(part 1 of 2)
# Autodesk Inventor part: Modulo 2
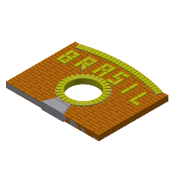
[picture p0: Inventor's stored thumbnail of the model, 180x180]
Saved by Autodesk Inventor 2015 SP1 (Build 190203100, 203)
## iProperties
Created: 2015-04
Part Number: Modulo 2
Material: Generic
Document SubType Name: Modeling
Designer: treina2
Density: 1 g/cm^3
Appearance: Default
Author: treina2
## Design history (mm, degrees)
sketch "Sketch1"
  geometry: L1 (740, 1360)-(740, 1418) reference; L2 (954, 1088)-(954, 1146) reference; L3 (740, 1088)-(740, 1146) reference; L4 (740, 1292)-(740, 1350) reference; L5 (954, 1224)-(954, 1282) reference; L6 (954, 1360)-(954, 1418) reference; L7 (954, 1292)-(954, 1350) reference; L8 (954, 1156)-(954, 1214) reference; L9 (740, 1156)-(740, 1214) reference; L10 (740, 1224)-(740, 1282) reference; L11 (1990, 534)-(1990, 544) reference; L12 (1990, 1350)-(1990, 1360) reference; L13 (740, 262)-(500, 262) reference; L14 (500, 262)-(500, 204) reference; L15 (1875, 136)-(1990, 136) reference; L16 (1990, 136)-(1990, 194) reference; L17 (1990, 194)-(1875, 194) reference; L18 (1875, 194)-(1875, 136) reference; L19 (250, 68)-(490, 68) reference; L20 (490, 68)-(490, 126) reference; L21 (490, 126)-(250, 126) reference; L22 (250, 126)-(250, 68) reference; L23 (750, 68)-(777.045, 68) reference; L24 (1250, 204)-(1490, 204) reference; L25 (1490, 204)-(1490, 262) reference; L26 (1490, 262)-(1250, 262) reference; L27 (1250, 262)-(1250, 204) reference; L28 (1500, 204)-(1740, 204) reference; L29 (1740, 204)-(1740, 262) reference; L30 (1740, 262)-(1500, 262) reference; L31 (1500, 262)-(1500, 204) reference; L32 (125, 136)-(365, 136) reference; L33 (365, 136)-(365, 194) reference; L34 (365, 194)-(125, 194) reference; L35 (125, 194)-(125, 136) reference; L36 (0, 476)-(240, 476) reference; L37 (240, 476)-(240, 534) reference; L38 (240, 534)-(0, 534) reference; L39 (0, 534)-(0, 476) reference; L40 (115, 408)-(0, 408) reference; L41 (0, 408)-(0, 466) reference; L42 (0, 466)-(115, 466) reference; L43 (115, 466)-(115, 408) reference; L44 (1750, 1020)-(1990, 1020) reference; L45 (1990, 1020)-(1990, 1078) reference; L46 (1990, 1078)-(1750, 1078) reference; L47 (1750, 1078)-(1750, 1020) reference; L48 (375, 680)-(570.34, 680) reference; L49 (1500, 884)-(1740, 884) reference; L50 (1740, 884)-(1740, 942) reference; L51 (1740, 942)-(1500, 942) reference; L52 (1500, 942)-(1500, 884) reference; L53 (1750, 884)-(1990, 884) reference; L54 (1990, 884)-(1990, 942) reference; L55 (1990, 942)-(1750, 942) reference; L56 (1750, 942)-(1750, 884) reference; L57 (1250, 1292)-(1422, 1292) reference; L58 (750, 1020)-(764.401, 1020) reference; L59 (250, 1214)-(250, 1156) reference; L60 (250, 1156)-(308, 1156) reference; L61 (750, 1258)-(750, 1418) reference; L62 (750, 1418)-(808, 1418) reference; L63 (808, 1418)-(808, 1258) reference; L64 (808, 1258)-(750, 1258) reference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; C1 r 300 at (995, 663) reference; C2 r 300 at (995, 663) reference; C3 r 300 at (995, 663) reference; C4 r 300 at (995, 663) reference; C5 r 300 at (995, 663) reference; C6 r 300 at (995, 663) reference; A1 r 425 centre (995, 663) between (749.611, 1010) and (683.385, 952) reference; A2 r 2840.721 centre (995, -1354.721) between (490, 1440.752) and (423.896, 1428) reference; A3 r 425 centre (995, 663) between (1411.413, 748) and (1395.22, 806) reference; A4 r 425 centre (995, 663) between (1419.66, 680) and (1413.33, 738) reference; A5 r 425 centre (995, 663) between (863.689, 258.794) and (990, 238.029) reference; A6 r 425 centre (995, 663) between (594.78, 806) and (578.587, 748) reference; A7 r 2840.721 centre (995, -1354.721) between (1615, 1417.516) and (1612.83, 1418) reference; A8 r 425 centre (995, 663) between (903.348, 1078) and (764.401, 1020) reference; A9 r 425 centre (995, 663) between (1376.649, 476) and (1399.949, 534) reference; A10 r 425 centre (995, 663) between (662.735, 398) and (718.783, 340) reference; A11 r 425 centre (995, 663) between (1358.021, 884) and (1315.599, 942) reference; A12 r 425 centre (995, 663) between (1365, 872.105) and (1363.923, 874) reference; A13 r 425 centre (995, 663) between (1225.599, 1020) and (1086.652, 1078) reference; A14 r 425 centre (995, 663) between (1403, 544) and (1415.6, 602) reference; A15 r 425 centre (995, 663) between (1416.929, 612) and (1419.942, 670) reference; A16 r 425 centre (995, 663) between (1161.565, 272) and (1259.076, 330) reference; A17 r 425 centre (995, 663) between (1271.217, 340) and (1327.265, 398) reference; A18 r 425 centre (995, 663) between (1335, 408) and (1365, 453.895) reference; A19 r 425 centre (995, 663) between (574.4, 602) and (587, 544) reference; A20 r 425 centre (995, 663) between (590.051, 534) and (613.351, 476) reference; A21 r 425 centre (995, 663) between (1000, 238.029) and (1126.311, 258.794) reference; A22 r 425 centre (995, 663) between (576.67, 738) and (570.34, 680) reference; A23 r 425 centre (995, 663) between (730.924, 330) and (828.435, 272) reference; A24 r 425 centre (995, 663) between (615, 853.329) and (598.495, 816) reference; A25 r 425 centre (995, 663) between (626.077, 874) and (625, 872.105) reference; A26 r 2840.721 centre (995, -1354.721) between (1831.651, 1360) and (1625, 1415.26) reference; A27 r 425 centre (995, 663) between (674.401, 942) and (631.979, 884) reference; A28 r 2840.721 centre (995, -1354.721) between (365, 1415.26) and (158.349, 1360) reference; A29 r 2840.721 centre (995, -1354.721) between (990, 1485.996) and (750, 1475.415) reference; A30 r 2840.721 centre (995, -1354.721) between (740, 1474.532) and (500, 1442.54) reference; A31 r 2840.721 centre (995, -1354.721) between (377.17, 1418) and (375, 1417.516) reference; A32 r 425 centre (995, 663) between (570.058, 670) and (573.071, 612) reference; A33 r 425 centre (995, 663) between (1391.505, 816) and (1375, 853.329) reference; A34 r 425 centre (995, 663) between (625, 453.895) and (655, 408) reference; A35 r 425 centre (995, 663) between (1306.615, 952) and (1240.389, 1010) reference; A36 r 2840.721 centre (995, -1354.721) between (1490, 1442.54) and (1250, 1474.532) reference; A37 r 2840.721 centre (995, -1354.721) between (1240, 1475.415) and (1000, 1485.996) reference; A38 r 2840.721 centre (995, -1354.721) between (1566.104, 1428) and (1500, 1440.752) reference; 1 further point
  constraints: 2472 end point, 508 horizontal, 481 vertical, 127 point on line, 76 point on circle, 44 centre point, 1 midpoint, 1471 other
extrude "Extrusion1" new body sketch "Sketch1" distance "d0" = 115 (= T_P_L); taper "d1" = 0 deg
extrude "Extrusion2" new body sketch "Sketch1" distance "d2" = 115 (= T_P_L); taper "d3" = 0 deg
extrude "Extrusion3" new body sketch "Sketch1" distance "d4" = 115 (= T_P_L); taper "d5" = 0 deg
extrude "Extrusion4" new body sketch "Sketch1" distance "d6" = 115 (= T_P_L); taper "d7" = 0 deg
extrude "Extrusion6" new body sketch "Sketch1" distance "d10" = 115 (= T_P_L); taper "d11" = 0 deg
extrude "Extrusion7" new body sketch "Sketch1" distance "d12" = 115 (= T_P_L); taper "d13" = 0 deg
extrude "Extrusion8" new body sketch "Sketch1" distance "d14" = 115 (= T_P_L); taper "d15" = 0 deg
extrude "Extrusion9" new body sketch "Sketch1" distance "d16" = 115 (= T_P_L); taper "d17" = 0 deg
extrude "Extrusion10" new body sketch "Sketch1" distance "d18" = 115 (= T_P_L); taper "d19" = 0 deg
extrude "Extrusion11" new body sketch "Sketch1" distance "d20" = 115 (= T_P_L); taper "d21" = 0 deg
extrude "Extrusion12" new body sketch "Sketch1" distance "d22" = 115 (= T_P_L); taper "d23" = 0 deg
extrude "Extrusion13" new body sketch "Sketch1" distance "d24" = 115 (= T_P_L); taper "d25" = 0 deg
extrude "Extrusion14" new body sketch "Sketch1" distance "d26" = 115 (= T_P_L); taper "d27" = 0 deg
extrude "Extrusion15" new body sketch "Sketch1" distance "d28" = 115 (= T_P_L); taper "d29" = 0 deg
pattern_linear "Rectangular Pattern1" dims "d32" = 136 (= 2 x T_P_P + 2 x GAP)
pattern_linear "Rectangular Pattern2" dims "d35" = 136 (= 2 x T_P_P + 2 x GAP)
pattern_linear "Rectangular Pattern3" dims "d38" = 136 (= 2 x T_P_P + 2 x GAP)
pattern_linear "Rectangular Pattern4" dims "d41" = 136 (= 2 x T_P_P + 2 x GAP)
pattern_linear "Rectangular Pattern5" dims "d44" = 136 (= 2 x T_P_P + 2 x GAP)
pattern_linear "Rectangular Pattern6" dims "d47" = 136 (= 2 x T_P_P + 2 x GAP)
extrude "Extrusion16" new body sketch "Sketch1" distance "d48" = 115 (= T_P_L); taper "d49" = 0 deg
extrude "Extrusion17" new body sketch "Sketch1" distance "d50" = 115 (= T_P_L); taper "d51" = 0 deg
extrude "Extrusion18" new body sketch "Sketch1" distance "d52" = 115 (= T_P_L); taper "d53" = 0 deg
pattern_linear "Rectangular Pattern7" dims "d56" = 136 (= 2 x T_P_P + 2 x GAP)
pattern_linear "Rectangular Pattern8" dims "d59" = 136 (= 2 x T_P_P + 2 x GAP)
pattern_linear "Rectangular Pattern9" dims "d62" = 136 (= 2 x T_P_P + 2 x GAP)
pattern_linear "Rectangular Pattern10" dims "d65" = 136 (= 2 x T_P_P + 2 x GAP)
pattern_linear "Rectangular Pattern11" dims "d68" = 136 (= 2 x T_P_P + 2 x GAP)
extrude "Extrusion19" new body sketch "Sketch1" distance "d69" = 115 (= T_P_L); taper "d70" = 0 deg
extrude "Extrusion20" new body sketch "Sketch1" distance "d71" = 115 (= T_P_L); taper "d72" = 0 deg
extrude "Extrusion21" new body sketch "Sketch1" distance "d73" = 115 (= T_P_L); taper "d74" = 0 deg
extrude "Extrusion22" new body sketch "Sketch1" distance "d75" = 115 (= T_P_L); taper "d76" = 0 deg
extrude "Extrusion25" new body sketch "Sketch1" distance "d81" = 115 (= T_P_L); taper "d82" = 0 deg
extrude "Extrusion26" new body sketch "Sketch1" distance "d83" = 115 (= T_P_L); taper "d84" = 0 deg
extrude "Extrusion27" new body sketch "Sketch1" distance "d85" = 115 (= T_P_L); taper "d86" = 0 deg
extrude "Extrusion28" new body sketch "Sketch1" distance "d87" = 115 (= T_P_L); taper "d88" = 0 deg
extrude "Extrusion29" new body sketch "Sketch1" distance "d89" = 115 (= T_P_L); taper "d90" = 0 deg
extrude "Extrusion30" new body sketch "Sketch1" distance "d91" = 115 (= T_P_L); taper "d92" = 0 deg
extrude "Extrusion31" new body sketch "Sketch1" distance "d93" = 115 (= T_P_L); taper "d94" = 0 deg
extrude "Extrusion32" new body sketch "Sketch1" distance "d95" = 115 (= T_P_L); taper "d96" = 0 deg
extrude "Extrusion33" new body sketch "Sketch1" distance "d97" = 115 (= T_P_L); taper "d98" = 0 deg
extrude "Extrusion34" new body sketch "Sketch1" distance "d99" = 115 (= T_P_L); taper "d100" = 0 deg
extrude "Extrusion35" new body sketch "Sketch1" distance "d101" = 115 (= T_P_L); taper "d102" = 0 deg
extrude "Extrusion36" new body sketch "Sketch1" distance "d103" = 115 (= T_P_L); taper "d104" = 0 deg
extrude "Extrusion37" new body sketch "Sketch1" distance "d105" = 115 (= T_P_L); taper "d106" = 0 deg
extrude "Extrusion38" new body sketch "Sketch1" distance "d107" = 115 (= T_P_L); taper "d108" = 0 deg
extrude "Extrusion39" new body sketch "Sketch1" distance "d109" = 115 (= T_P_L); taper "d110" = 0 deg
extrude "Extrusion40" new body sketch "Sketch1" distance "d111" = 115 (= T_P_L); taper "d112" = 0 deg
extrude "Extrusion41" new body sketch "Sketch1" distance "d113" = 115 (= T_P_L); taper "d114" = 0 deg
extrude "Extrusion42" new body sketch "Sketch1" distance "d115" = 115 (= T_P_L); taper "d116" = 0 deg
extrude "Extrusion43" new body sketch "Sketch1" distance "d117" = 115 (= T_P_L); taper "d118" = 0 deg
extrude "Extrusion44" new body sketch "Sketch1" distance "d119" = 115 (= T_P_L); taper "d120" = 0 deg
extrude "Extrusion45" new body sketch "Sketch1" distance "d121" = 115 (= T_P_L); taper "d122" = 0 deg
extrude "Extrusion46" new body sketch "Sketch1" distance "d123" = 115 (= T_P_L); taper "d124" = 0 deg
extrude "Extrusion47" new body sketch "Sketch1" distance "d125" = 115 (= T_P_L); taper "d126" = 0 deg
extrude "Extrusion48" new body sketch "Sketch1" distance "d127" = 115 (= T_P_L); taper "d128" = 0 deg
extrude "Extrusion49" new body sketch "Sketch1" distance "d129" = 115 (= T_P_L); taper "d130" = 0 deg
extrude "Extrusion50" new body sketch "Sketch1" distance "d131" = 115 (= T_P_L); taper "d132" = 0 deg
extrude "Extrusion51" new body sketch "Sketch1" distance "d133" = 115 (= T_P_L); taper "d134" = 0 deg
extrude "Extrusion52" new body sketch "Sketch1" distance "d135" = 115 (= T_P_L); taper "d136" = 0 deg
extrude "Extrusion53" new body sketch "Sketch1" distance "d137" = 115 (= T_P_L); taper "d138" = 0 deg
pattern_linear "Rectangular Pattern12" dims "d141" = 136 (= 2 x T_P_P + 2 x GAP)
pattern_linear "Rectangular Pattern13" dims "d144" = 136 (= 2 x T_P_P + 2 x GAP)
extrude "Extrusion54" new body sketch "Sketch1" distance "d145" = 115 (= T_P_L); taper "d146" = 0 deg
extrude "Extrusion55" new body sketch "Sketch1" distance "d147" = 115 (= T_P_L); taper "d148" = 0 deg
extrude "Extrusion56" new body sketch "Sketch1" distance "d149" = 115 (= T_P_L); taper "d150" = 0 deg
extrude "Extrusion57" new body sketch "Sketch1" distance "d151" = 115 (= T_P_L); taper "d152" = 0 deg
extrude "Extrusion58" new body sketch "Sketch1" distance "d153" = 115 (= T_P_L); taper "d154" = 0 deg
extrude "Extrusion59" new body sketch "Sketch1" distance "d155" = 115 (= T_P_L); taper "d156" = 0 deg
extrude "Extrusion60" new body sketch "Sketch1" distance "d157" = 115 (= T_P_L); taper "d158" = 0 deg
extrude "Extrusion61" new body sketch "Sketch1" distance "d159" = 115 (= T_P_L); taper "d160" = 0 deg
extrude "Extrusion62" new body sketch "Sketch1" distance "d161" = 115 (= T_P_L); taper "d162" = 0 deg
pattern_linear "Rectangular Pattern14" dims "d165" = 68 (= T_P_P + GAP)
extrude "Extrusion63" new body sketch "Sketch1" distance "d166" = 115 (= T_P_L); taper "d167" = 0 deg
extrude "Extrusion64" new body sketch "Sketch1" distance "d168" = 115 (= T_P_L); taper "d169" = 0 deg
extrude "Extrusion65" new body sketch "Sketch1" distance "d170" = 115 (= T_P_L); taper "d171" = 0 deg
extrude "Extrusion66" new body sketch "Sketch1" distance "d172" = 115 (= T_P_L); taper "d173" = 0 deg
extrude "Extrusion67" new body sketch "Sketch1" distance "d174" = 115 (= T_P_L); taper "d175" = 0 deg
extrude "Extrusion68" new body sketch "Sketch1" distance "d176" = 115 (= T_P_L); taper "d177" = 0 deg
extrude "Extrusion69" new body sketch "Sketch1" distance "d178" = 115 (= T_P_L); taper "d179" = 0 deg
extrude "Extrusion70" new body sketch "Sketch1" distance "d180" = 115 (= T_P_L); taper "d181" = 0 deg
pattern_linear "Rectangular Pattern15" dims "d184" = 68 (= T_P_P + GAP)
extrude "Extrusion71" new body sketch "Sketch1" distance "d185" = 115 (= T_P_L); taper "d186" = 0 deg
extrude "Extrusion72" new body sketch "Sketch1" distance "d187" = 115 (= T_P_L); taper "d188" = 0 deg
extrude "Extrusion73" new body sketch "Sketch1" distance "d189" = 115 (= T_P_L); taper "d190" = 0 deg
extrude "Extrusion74" new body sketch "Sketch1" distance "d191" = 115 (= T_P_L); taper "d192" = 0 deg
extrude "Extrusion75" new body sketch "Sketch1" distance "d193" = 115 (= T_P_L); taper "d194" = 0 deg
extrude "Extrusion76" new body sketch "Sketch1" distance "d195" = 115 (= T_P_L); taper "d196" = 0 deg
extrude "Extrusion77" new body sketch "Sketch1" distance "d197" = 115 (= T_P_L); taper "d198" = 0 deg
extrude "Extrusion78" new body sketch "Sketch1" distance "d199" = 115 (= T_P_L); taper "d200" = 0 deg
extrude "Extrusion79" new body sketch "Sketch1" distance "d201" = 115 (= T_P_L); taper "d202" = 0 deg
extrude "Extrusion80" new body sketch "Sketch1" distance "d203" = 115 (= T_P_L); taper "d204" = 0 deg
extrude "Extrusion81" new body sketch "Sketch1" distance "d205" = 115 (= T_P_L); taper "d206" = 0 deg
extrude "Extrusion82" new body sketch "Sketch1" distance "d207" = 115 (= T_P_L); taper "d208" = 0 deg
extrude "Extrusion83" new body sketch "Sketch1" distance "d209" = 115 (= T_P_L); taper "d210" = 0 deg
extrude "Extrusion84" new body sketch "Sketch1" distance "d211" = 115 (= T_P_L); taper "d212" = 0 deg
extrude "Extrusion85" new body sketch "Sketch1" distance "d213" = 115 (= T_P_L); taper "d214" = 0 deg
extrude "Extrusion86" new body sketch "Sketch1" distance "d215" = 115 (= T_P_L); taper "d216" = 0 deg
extrude "Extrusion87" new body sketch "Sketch1" distance "d217" = 115 (= T_P_L); taper "d218" = 0 deg
extrude "Extrusion88" new body sketch "Sketch1" distance "d219" = 115 (= T_P_L); taper "d220" = 0 deg
extrude "Extrusion89" new body sketch "Sketch1" distance "d221" = 115 (= T_P_L); taper "d222" = 0 deg
extrude "Extrusion90" new body sketch "Sketch1" distance "d223" = 115 (= T_P_L); taper "d224" = 0 deg
extrude "Extrusion91" new body sketch "Sketch1" distance "d225" = 115 (= T_P_L); taper "d226" = 0 deg
extrude "Extrusion92" new body sketch "Sketch1" distance "d227" = 115 (= T_P_L); taper "d228" = 0 deg
extrude "Extrusion93" new body sketch "Sketch1" distance "d229" = 115 (= T_P_L); taper "d230" = 0 deg
extrude "Extrusion94" new body sketch "Sketch1" distance "d231" = 115 (= T_P_L); taper "d232" = 0 deg
extrude "Extrusion95" new body sketch "Sketch1" distance "d233" = 115 (= T_P_L); taper "d234" = 0 deg
extrude "Extrusion96" new body sketch "Sketch1" distance "d235" = 115 (= T_P_L); taper "d236" = 0 deg
extrude "Extrusion97" new body sketch "Sketch1" distance "d237" = 115 (= T_P_L); taper "d238" = 0 deg
extrude "Extrusion98" new body sketch "Sketch1" distance "d239" = 115 (= T_P_L); taper "d240" = 0 deg
extrude "Extrusion99" new body sketch "Sketch1" distance "d241" = 115 (= T_P_L); taper "d242" = 0 deg
extrude "Extrusion100" new body sketch "Sketch1" distance "d243" = 115 (= T_P_L); taper "d244" = 0 deg
extrude "Extrusion101" new body sketch "Sketch1" distance "d245" = 115 (= T_P_L); taper "d246" = 0 deg
extrude "Extrusion102" new body sketch "Sketch1" distance "d247" = 115 (= T_P_L); taper "d248" = 0 deg
extrude "Extrusion103" new body sketch "Sketch1" distance "d249" = 115 (= T_P_L); taper "d250" = 0 deg
extrude "Extrusion104" new body sketch "Sketch1" distance "d251" = 115 (= T_P_L); taper "d252" = 0 deg
extrude "Extrusion105" new body sketch "Sketch1" distance "d253" = 115 (= T_P_L); taper "d254" = 0 deg
workplane "Work Plane1"
sketch "Sketch2"
  geometry: L1 (0, 1292)-(0, 1350); L2 (214, 1020)-(214, 1078); L3 (0, 1020)-(0, 1078); L4 (0, 1224)-(0, 1282); L5 (214, 1156)-(214, 1214); L6 (214, 1292)-(214, 1350); L7 (214, 1224)-(214, 1282); L8 (214, 1088)-(214, 1146); L9 (0, 1088)-(0, 1146); L10 (0, 1156)-(0, 1214); L11 (1250, 466)-(1250, 476); L12 (1250, 1282)-(1250, 1292); L13 (0, 194)-(-240, 194); L14 (-240, 194)-(-240, 136); L15 (1135, 68)-(1250, 68); L16 (1250, 68)-(1250, 126); L17 (1250, 126)-(1135, 126); L18 (1135, 126)-(1135, 68); L19 (-490, 0)-(-250, 0); L20 (-250, 0)-(-250, 58); L21 (-250, 58)-(-490, 58); L22 (-490, 58)-(-490, 0); L23 (10, 0)-(37.045, 0); L24 (510, 136)-(750, 136); L25 (750, 136)-(750, 194); L26 (750, 194)-(510, 194); L27 (510, 194)-(510, 136); L28 (760, 136)-(1000, 136); L29 (1000, 136)-(1000, 194); L30 (1000, 194)-(760, 194); L31 (760, 194)-(760, 136); L32 (-615, 68)-(-375, 68); L33 (-375, 68)-(-375, 126); L34 (-375, 126)-(-615, 126); L35 (-615, 126)-(-615, 68); L36 (-740, 408)-(-500, 408); L37 (-500, 408)-(-500, 466); L38 (-500, 466)-(-740, 466); L39 (-740, 466)-(-740, 408); L40 (-625, 340)-(-740, 340); L41 (-740, 340)-(-740, 398); L42 (-740, 398)-(-625, 398); L43 (-625, 398)-(-625, 340); L44 (1010, 952)-(1250, 952); L45 (1250, 952)-(1250, 1010); L46 (1250, 1010)-(1010, 1010); L47 (1010, 1010)-(1010, 952); L48 (-365, 612)-(-169.66, 612); L49 (760, 816)-(1000, 816); L50 (1000, 816)-(1000, 874); L51 (1000, 874)-(760, 874); L52 (760, 874)-(760, 816); L53 (1010, 816)-(1250, 816); L54 (1250, 816)-(1250, 874); L55 (1250, 874)-(1010, 874); L56 (1010, 874)-(1010, 816); L57 (510, 1224)-(682, 1224); L58 (10, 952)-(24.401, 952); L59 (-490, 1146)-(-490, 1088); L60 (-490, 1088)-(-432, 1088); L61 (10, 1190)-(10, 1350); L62 (10, 1350)-(68, 1350); L63 (68, 1350)-(68, 1190); L64 (68, 1190)-(10, 1190)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; C1 r 300 at (255, 595); C2 r 300 at (255, 595); C3 r 300 at (255, 595); C4 r 300 at (255, 595); C5 r 300 at (255, 595); C6 r 300 at (255, 595); A1 r 425 centre (255, 595) between (9.611, 942) and (-56.615, 884); A2 r 2840.721 centre (255, -1422.721) between (-250, 1372.752) and (-316.104, 1360); A3 r 425 centre (255, 595) between (671.413, 680) and (655.22, 738); A4 r 425 centre (255, 595) between (679.66, 612) and (673.33, 670); A5 r 425 centre (255, 595) between (123.689, 190.794) and (250, 170.029); A6 r 425 centre (255, 595) between (-145.22, 738) and (-161.413, 680); A7 r 2840.721 centre (255, -1422.721) between (875, 1349.516) and (872.83, 1350); A8 r 425 centre (255, 595) between (163.348, 1010) and (24.401, 952); A9 r 425 centre (255, 595) between (636.649, 408) and (659.949, 466); A10 r 425 centre (255, 595) between (-77.265, 330) and (-21.217, 272); A11 r 425 centre (255, 595) between (618.021, 816) and (575.599, 874); A12 r 425 centre (255, 595) between (625, 804.105) and (623.923, 806); A13 r 425 centre (255, 595) between (485.599, 952) and (346.652, 1010); A14 r 425 centre (255, 595) between (663, 476) and (675.6, 534); A15 r 425 centre (255, 595) between (676.929, 544) and (679.942, 602); A16 r 425 centre (255, 595) between (421.565, 204) and (519.076, 262); A17 r 425 centre (255, 595) between (531.217, 272) and (587.265, 330); A18 r 425 centre (255, 595) between (595, 340) and (625, 385.895); A19 r 425 centre (255, 595) between (-165.6, 534) and (-153, 476); A20 r 425 centre (255, 595) between (-149.949, 466) and (-126.649, 408); A21 r 425 centre (255, 595) between (260, 170.029) and (386.311, 190.794); A22 r 425 centre (255, 595) between (-163.33, 670) and (-169.66, 612); A23 r 425 centre (255, 595) between (-9.076, 262) and (88.435, 204); A24 r 425 centre (255, 595) between (-125, 785.329) and (-141.505, 748); A25 r 425 centre (255, 595) between (-113.923, 806) and (-115, 804.105); A26 r 2840.721 centre (255, -1422.721) between (1091.651, 1292) and (885, 1347.26); A27 r 425 centre (255, 595) between (-65.599, 874) and (-108.021, 816); A28 r 2840.721 centre (255, -1422.721) between (-375, 1347.26) and (-581.651, 1292); A29 r 2840.721 centre (255, -1422.721) between (250, 1417.996) and (10, 1407.415); A30 r 2840.721 centre (255, -1422.721) between (0, 1406.532) and (-240, 1374.54); A31 r 2840.721 centre (255, -1422.721) between (-362.83, 1350) and (-365, 1349.516); A32 r 425 centre (255, 595) between (-169.942, 602) and (-166.929, 544); A33 r 425 centre (255, 595) between (651.505, 748) and (635, 785.329); A34 r 425 centre (255, 595) between (-115, 385.895) and (-85, 340); A35 r 425 centre (255, 595) between (566.615, 884) and (500.389, 942); A36 r 2840.721 centre (255, -1422.721) between (750, 1374.54) and (510, 1406.532); A37 r 2840.721 centre (255, -1422.721) between (500, 1407.415) and (260, 1417.996); A38 r 2840.721 centre (255, -1422.721) between (826.104, 1360) and (760, 1372.752); 2 further points
  constraints: 2472 end point, 127 point on line, 76 point on circle, 44 centre point, 1 midpoint
extrude "Extrusion106" new body sketch "Sketch2" distance "d255" = 15; taper "d257" = 0 deg; dims "d256" = 140 (derived), "d258" = 0
extrude "Extrusion107" new body sketch "Sketch2" distance "d259" = 15; taper "d261" = 0 deg; dims "d260" = 140 (derived), "d262" = 0
extrude "Extrusion108" new body sketch "Sketch2" distance "d263" = 15; taper "d265" = 0 deg; dims "d264" = 140 (derived), "d266" = 0
workplane "Work Plane2"
sketch "Sketch3"
  geometry: L1 (906.204, 951.021)-(963.017, 962.697) reference; L2 (963.017, 962.697)-(939.867, 1075.343) reference; L3 (939.867, 1075.343)-(883.055, 1063.667) reference; L4 (883.055, 1063.667)-(906.204, 951.021) reference; L5 (939.867, 1075.343)-(883.055, 1063.667); L6 (906.204, 951.021)-(883.055, 1063.667); L7 (963.017, 962.697)-(906.204, 951.021); L8 (939.867, 1075.343)-(963.017, 962.697); L9 (903.343, 950.124)-(850.043, 927.251); L10 (850.043, 927.251)-(804.693, 1032.931); L11 (857.992, 1055.804)-(903.343, 950.124); L12 (857.992, 1055.804)-(804.693, 1032.931); L13 (847.422, 925.796)-(799.817, 892.662); L14 (799.817, 892.662)-(734.122, 987.05); L15 (781.726, 1020.184)-(847.422, 925.796); L16 (781.726, 1020.184)-(734.122, 987.05); L17 (797.542, 890.709)-(757.582, 848.671); L18 (757.582, 848.671)-(674.231, 927.902); L19 (714.191, 969.94)-(797.542, 890.709); L20 (714.191, 969.94)-(674.231, 927.902); L21 (755.747, 846.3)-(725.067, 797.079); L22 (725.067, 797.079)-(627.473, 857.909); L23 (658.153, 907.131)-(755.747, 846.3); L24 (658.153, 907.131)-(627.473, 857.909); L25 (723.746, 794.386)-(703.603, 739.997); L26 (703.603, 739.997)-(595.761, 779.937); L27 (615.905, 834.326)-(723.746, 794.386); L28 (615.905, 834.326)-(595.761, 779.937); L29 (702.851, 737.094)-(694.068, 679.763); L30 (694.068, 679.763)-(580.394, 697.177); L31 (589.177, 754.508)-(702.851, 737.094); L32 (589.177, 754.508)-(580.394, 697.177); L33 (693.916, 676.768)-(696.854, 618.842); L34 (696.854, 618.842)-(582.001, 613.018); L35 (579.064, 670.943)-(693.916, 676.768); L36 (579.064, 670.943)-(582.001, 613.018); L37 (697.308, 615.878)-(711.846, 559.73); L38 (711.846, 559.73)-(600.517, 530.905); L39 (585.979, 587.053)-(697.308, 615.878); L40 (585.979, 587.053)-(600.517, 530.905); L41 (712.887, 556.918)-(738.43, 504.845); L42 (738.43, 504.845)-(635.183, 454.2); L43 (609.64, 506.273)-(712.887, 556.918); L44 (609.64, 506.273)-(635.183, 454.2); L45 (740.016, 502.301)-(775.518, 456.436); L46 (775.518, 456.436)-(684.579, 386.044); L47 (649.077, 431.909)-(740.016, 502.301); L48 (649.077, 431.909)-(684.579, 386.044); L49 (777.584, 454.262)-(821.592, 416.483); L50 (821.592, 416.483)-(746.684, 329.226); L51 (702.676, 367.005)-(777.584, 454.262); L52 (702.676, 367.005)-(746.684, 329.226); L53 (824.053, 414.77)-(874.765, 386.622); L54 (874.765, 386.622)-(818.956, 286.072); L55 (768.244, 314.22)-(824.053, 414.77); L56 (768.244, 314.22)-(818.956, 286.072); L57 (877.521, 385.44)-(932.861, 368.077); L58 (932.861, 368.077)-(898.434, 258.351); L59 (843.094, 275.714)-(877.521, 385.44); L60 (843.094, 275.714)-(898.434, 258.351); L61 (935.798, 367.473)-(993.501, 361.605); L62 (993.501, 361.605)-(981.866, 247.195); L63 (924.164, 253.063)-(935.798, 367.473); L64 (924.164, 253.063)-(981.866, 247.195)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; C1 r 156.317 at (995, 663); A1 r 425 centre (995, 663) between (1000, 238.029) and (1126.311, 258.794) reference; A2 r 425 centre (995, 663) between (863.689, 258.794) and (990, 238.029) reference; 2 further points
  constraints: 248 end point, 3 collinear, 1 centre point, 1 coincident, 249 other
  dimensions: "d270" = 360 deg dimension on point (995, 663) L1.end (derived)
  node "Project Cut Edges1"
extrude "Extrusion109" new body sketch "Sketch3" distance "d272" = 115 (derived); taper "d273" = 0 deg
workplane "Work Plane3"
sketch "Sketch4"
  geometry: L1 (308, 1146)-(193, 1146) reference; L2 (308, 1088)-(308, 1146) reference; L3 (193, 1088)-(308, 1088) reference; L4 (193, 1146)-(193, 1112) reference; L5 (193, 1122)-(193, 1088) reference; L6 (183, 1282)-(183, 1122) reference; L7 (183, 1282)-(125, 1282) reference; L8 (125, 1122)-(125, 1282) reference; L9 (183, 1122)-(125, 1122) reference; L10 (125, 1112)-(183, 1112) reference; L11 (125, 952)-(125, 1112) reference; L12 (183, 1112)-(183, 952) reference; L13 (183, 952)-(125, 952) reference; L14 (308, 1020)-(250, 1020) reference; L15 (250, 1078)-(250, 1020) reference; L16 (308, 1078)-(250, 1078) reference; L17 (308, 1078)-(308, 1020) reference; L18 (308, 952)-(308, 1010) reference; L19 (308, 1010)-(193, 1010) reference; L20 (193, 952)-(308, 952) reference; L21 (193, 1010)-(193, 952) reference; L22 (250, 1156)-(308, 1156) reference; L23 (308, 1214)-(308, 1156) reference; L24 (250, 1214)-(308, 1214) reference; L25 (250, 1214)-(250, 1156) reference; L26 (240, 1224)-(308, 1224) reference; L27 (308, 1224)-(308, 1282) reference; L28 (308, 1282)-(193, 1282) reference; L29 (193, 1282)-(193, 1224) reference; L30 (193, 1224)-(308, 1224) reference; L31 (490, 1292)-(490, 1350) reference; L32 (432, 1350)-(490, 1350) reference; L33 (432, 1282)-(432, 1350) reference; L34 (432, 1190)-(432, 1350) reference; L35 (490, 1350)-(490, 1190) reference; L36 (490, 1190)-(432, 1190) reference; L37 (432, 1180)-(490, 1180) reference; L38 (490, 1180)-(490, 1020) reference; L39 (432, 1020)-(432, 1180) reference; L40 (490, 1020)-(432, 1020) reference; L41 (500, 1135)-(547, 1088) reference; L42 (500, 1146)-(500, 1135) reference; L43 (571.024, 1146)-(500, 1146) reference; L44 (615, 1102.024)-(571.024, 1146) reference; L45 (615, 1020)-(615, 1088) reference; L46 (547, 1088)-(615, 1020) reference; L47 (615, 1088)-(615, 1102.024) reference; L48 (615, 1156)-(615, 1214) reference; L49 (615, 1214)-(500, 1214) reference; L50 (500, 1156)-(615, 1156) reference; L51 (500, 1190)-(500, 1156) reference; L52 (500, 1214)-(500, 1180) reference; L53 (567.5, 1224)-(615, 1224) reference; L54 (567.5, 1224)-(567.5, 1282) reference; L55 (615, 1282)-(615, 1224) reference; L56 (615, 1282)-(567.5, 1282) reference; L57 (500, 1292)-(615, 1292) reference; L58 (615, 1292)-(615, 1350) reference; L59 (500, 1350)-(500, 1292) reference; L60 (615, 1350)-(500, 1350) reference; L61 (750, 1418)-(808, 1418) reference; L62 (750, 1258)-(750, 1418) reference; L63 (808, 1258)-(750, 1258) reference; L64 (808, 1418)-(808, 1258) reference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; 1 further point
extrude "Extrusion110" new body sketch "Sketch4" distance "d278" = 115 (derived); taper "d279" = 0 deg
extrude "Extrusion111" new body sketch "Sketch4" distance "d280" = 115 (derived); taper "d281" = 0 deg
extrude "Extrusion112" new body sketch "Sketch4" distance "d282" = 115 (derived); taper "d283" = 0 deg
extrude "Extrusion113" new body sketch "Sketch4" distance "d284" = 115 (derived); taper "d285" = 0 deg
pattern_linear "Rectangular Pattern16" dims "d288" = 136 (derived)
pattern_linear "Rectangular Pattern17" dims "d291" = 136 (derived)
extrude "Extrusion114" new body sketch "Sketch4" distance "d292" = 115 (derived); taper "d293" = 0 deg
extrude "Extrusion115" new body sketch "Sketch4" distance "d294" = 115 (derived); taper "d295" = 0 deg
extrude "Extrusion116" new body sketch "Sketch4" distance "d296" = 115 (derived); taper "d297" = 0 deg
extrude "Extrusion117" new body sketch "Sketch4" distance "d298" = 115 (derived); taper "d299" = 0 deg
extrude "Extrusion118" new body sketch "Sketch4" distance "d300" = 115 (derived); taper "d301" = 0 deg
extrude "Extrusion119" new body sketch "Sketch4" distance "d302" = 115 (derived); taper "d303" = 0 deg
extrude "Extrusion120" new body sketch "Sketch4" distance "d304" = 115 (derived); taper "d305" = 0 deg
extrude "Extrusion121" new body sketch "Sketch4" distance "d306" = 115 (derived); taper "d307" = 0 deg
extrude "Extrusion122" new body sketch "Sketch4" distance "d308" = 115 (derived); taper "d309" = 0 deg
extrude "Extrusion123" new body sketch "Sketch4" distance "d310" = 115 (derived); taper "d311" = 0 deg
extrude "Extrusion124" new body sketch "Sketch4" distance "d312" = 115 (derived); taper "d313" = 0 deg
extrude "Extrusion125" new body sketch "Sketch4" distance "d314" = 115 (derived); taper "d315" = 0 deg
extrude "Extrusion126" new body sketch "Sketch4" distance "d316" = 115 (derived); taper "d317" = 0 deg
extrude "Extrusion127" new body sketch "Sketch4" distance "d318" = 115 (derived); taper "d319" = 0 deg
extrude "Extrusion128" new body sketch "Sketch4" distance "d320" = 115 (derived); taper "d321" = 0 deg
extrude "Extrusion129" new body sketch "Sketch4" distance "d322" = 115 (derived); taper "d323" = 0 deg
extrude "Extrusion130" new body sketch "Sketch4" distance "d324" = 115 (derived); taper "d325" = 0 deg
extrude "Extrusion131" new body sketch "Sketch4" distance "d326" = 115 (derived); taper "d327" = 0 deg
extrude "Extrusion132" new body sketch "Sketch4" distance "d328" = 115 (derived); taper "d329" = 0 deg
extrude "Extrusion133" new body sketch "Sketch4" distance "d330" = 115 (derived); taper "d331" = 0 deg
extrude "Extrusion134" new body sketch "Sketch4" distance "d332" = 115 (derived); taper "d333" = 0 deg
extrude "Extrusion135" new body sketch "Sketch4" distance "d334" = 115 (derived); taper "d335" = 0 deg
sketch "Sketch5"
  geometry: L1 (740, 1360)-(740, 1418); L2 (954, 1088)-(954, 1146); L3 (740, 1088)-(740, 1146); L4 (740, 1292)-(740, 1350); L5 (954, 1224)-(954, 1282); L6 (954, 1360)-(954, 1418); L7 (954, 1292)-(954, 1350); L8 (954, 1156)-(954, 1214); L9 (740, 1156)-(740, 1214); L10 (740, 1224)-(740, 1282); L11 (1990, 534)-(1990, 544); L12 (1990, 1350)-(1990, 1360); L13 (740, 262)-(500, 262); L14 (500, 262)-(500, 204); L15 (1875, 136)-(1990, 136); L16 (1990, 136)-(1990, 194); L17 (1990, 194)-(1875, 194); L18 (1875, 194)-(1875, 136); L19 (250, 68)-(490, 68); L20 (490, 68)-(490, 126); L21 (490, 126)-(250, 126); L22 (250, 126)-(250, 68); L23 (750, 68)-(777.045, 68); L24 (1250, 204)-(1490, 204); L25 (1490, 204)-(1490, 262); L26 (1490, 262)-(1250, 262); L27 (1250, 262)-(1250, 204); L28 (1500, 204)-(1740, 204); L29 (1740, 204)-(1740, 262); L30 (1740, 262)-(1500, 262); L31 (1500, 262)-(1500, 204); L32 (125, 136)-(365, 136); L33 (365, 136)-(365, 194); L34 (365, 194)-(125, 194); L35 (125, 194)-(125, 136); L36 (0, 476)-(240, 476); L37 (240, 476)-(240, 534); L38 (240, 534)-(0, 534); L39 (0, 534)-(0, 476); L40 (115, 408)-(0, 408); L41 (0, 408)-(0, 466); L42 (0, 466)-(115, 466); L43 (115, 466)-(115, 408); L44 (1750, 1020)-(1990, 1020); L45 (1990, 1020)-(1990, 1078); L46 (1990, 1078)-(1750, 1078); L47 (1750, 1078)-(1750, 1020); L48 (375, 680)-(570.34, 680); L49 (1500, 884)-(1740, 884); L50 (1740, 884)-(1740, 942); L51 (1740, 942)-(1500, 942); L52 (1500, 942)-(1500, 884); L53 (1750, 884)-(1990, 884); L54 (1990, 884)-(1990, 942); L55 (1990, 942)-(1750, 942); L56 (1750, 942)-(1750, 884); L57 (1250, 1292)-(1422, 1292); L58 (750, 1020)-(764.401, 1020); L59 (250, 1214)-(250, 1156); L60 (250, 1156)-(308, 1156); L61 (750, 1258)-(750, 1418); L62 (750, 1418)-(808, 1418); L63 (808, 1418)-(808, 1258); L64 (808, 1258)-(750, 1258)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; C1 r 300 at (995, 663); C2 r 300 at (995, 663); C3 r 300 at (995, 663); C4 r 300 at (995, 663); C5 r 300 at (995, 663); C6 r 300 at (995, 663); A1 r 425 centre (995, 663) between (749.611, 1010) and (683.385, 952); A2 r 2840.721 centre (995, -1354.721) between (490, 1440.752) and (423.896, 1428); A3 r 425 centre (995, 663) between (1411.413, 748) and (1395.22, 806); A4 r 425 centre (995, 663) between (1419.66, 680) and (1413.33, 738); A5 r 425 centre (995, 663) between (863.689, 258.794) and (990, 238.029); A6 r 425 centre (995, 663) between (594.78, 806) and (578.587, 748); A7 r 2840.721 centre (995, -1354.721) between (1615, 1417.516) and (1612.83, 1418); A8 r 425 centre (995, 663) between (903.348, 1078) and (764.401, 1020); A9 r 425 centre (995, 663) between (1376.649, 476) and (1399.949, 534); A10 r 425 centre (995, 663) between (662.735, 398) and (718.783, 340); A11 r 425 centre (995, 663) between (1358.021, 884) and (1315.599, 942); A12 r 425 centre (995, 663) between (1365, 872.105) and (1363.923, 874); A13 r 425 centre (995, 663) between (1225.599, 1020) and (1086.652, 1078); A14 r 425 centre (995, 663) between (1403, 544) and (1415.6, 602); A15 r 425 centre (995, 663) between (1416.929, 612) and (1419.942, 670); A16 r 425 centre (995, 663) between (1161.565, 272) and (1259.076, 330); A17 r 425 centre (995, 663) between (1271.217, 340) and (1327.265, 398); A18 r 425 centre (995, 663) between (1335, 408) and (1365, 453.895); A19 r 425 centre (995, 663) between (574.4, 602) and (587, 544); A20 r 425 centre (995, 663) between (590.051, 534) and (613.351, 476); A21 r 425 centre (995, 663) between (1000, 238.029) and (1126.311, 258.794); A22 r 425 centre (995, 663) between (576.67, 738) and (570.34, 680); A23 r 425 centre (995, 663) between (730.924, 330) and (828.435, 272); A24 r 425 centre (995, 663) between (615, 853.329) and (598.495, 816); A25 r 425 centre (995, 663) between (626.077, 874) and (625, 872.105); A26 r 2840.721 centre (995, -1354.721) between (1831.651, 1360) and (1625, 1415.26); A27 r 425 centre (995, 663) between (674.401, 942) and (631.979, 884); A28 r 2840.721 centre (995, -1354.721) between (365, 1415.26) and (158.349, 1360); A29 r 2840.721 centre (995, -1354.721) between (990, 1485.996) and (750, 1475.415); A30 r 2840.721 centre (995, -1354.721) between (740, 1474.532) and (500, 1442.54); A31 r 2840.721 centre (995, -1354.721) between (377.17, 1418) and (375, 1417.516); A32 r 425 centre (995, 663) between (570.058, 670) and (573.071, 612); A33 r 425 centre (995, 663) between (1391.505, 816) and (1375, 853.329); A34 r 425 centre (995, 663) between (625, 453.895) and (655, 408); A35 r 425 centre (995, 663) between (1306.615, 952) and (1240.389, 1010); A36 r 2840.721 centre (995, -1354.721) between (1490, 1442.54) and (1250, 1474.532); A37 r 2840.721 centre (995, -1354.721) between (1240, 1475.415) and (1000, 1485.996); A38 r 2840.721 centre (995, -1354.721) between (1566.104, 1428) and (1500, 1440.752); 3 further points
  constraints: 2472 end point, 127 point on line, 76 point on circle, 44 centre point, 1 midpoint
extrude "Extrusion136" new body sketch "Sketch5" distance "d336" = 115 (derived); taper "d337" = 0 deg
extrude "Extrusion137" new body sketch "Sketch5" distance "d338" = 115 (derived); taper "d339" = 0 deg
extrude "Extrusion138" new body sketch "Sketch5" distance "d340" = 115 (derived); taper "d341" = 0 deg
extrude "Extrusion139" new body sketch "Sketch5" distance "d342" = 115 (derived); taper "d343" = 0 deg
extrude "Extrusion140" new body sketch "Sketch5" distance "d344" = 115 (derived); taper "d345" = 0 deg
extrude "Extrusion141" new body sketch "Sketch5" distance "d346" = 115 (derived); taper "d347" = 0 deg
extrude "Extrusion142" new body sketch "Sketch5" distance "d348" = 115 (derived); taper "d349" = 0 deg
extrude "Extrusion143" new body sketch "Sketch5" distance "d350" = 115 (derived); taper "d351" = 0 deg
extrude "Extrusion144" new body sketch "Sketch5" distance "d352" = 115 (derived); taper "d353" = 0 deg
extrude "Extrusion145" new body sketch "Sketch5" distance "d354" = 115 (derived); taper "d355" = 0 deg
extrude "Extrusion146" new body sketch "Sketch5" distance "d356" = 115 (derived); taper "d357" = 0 deg
extrude "Extrusion147" new body sketch "Sketch5" distance "d358" = 115 (derived); taper "d359" = 0 deg
extrude "Extrusion148" new body sketch "Sketch5" distance "d360" = 115 (derived); taper "d361" = 0 deg
extrude "Extrusion149" new body sketch "Sketch5" distance "d362" = 115 (derived); taper "d363" = 0 deg
extrude "Extrusion150" new body sketch "Sketch5" distance "d364" = 115 (derived); taper "d365" = 0 deg
extrude "Extrusion151" new body sketch "Sketch5" distance "d366" = 115 (derived); taper "d367" = 0 deg
extrude "Extrusion152" new body sketch "Sketch5" distance "d368" = 115 (derived); taper "d369" = 0 deg
extrude "Extrusion153" new body sketch "Sketch5" distance "d370" = 115 (derived); taper "d371" = 0 deg
extrude "Extrusion154" new body sketch "Sketch5" distance "d372" = 115 (derived); taper "d373" = 0 deg
extrude "Extrusion155" new body sketch "Sketch5" distance "d374" = 115 (derived); taper "d375" = 0 deg
extrude "Extrusion156" new body sketch "Sketch5" distance "d376" = 115 (derived); taper "d377" = 0 deg
extrude "Extrusion157" new body sketch "Sketch5" distance "d378" = 115 (derived); taper "d379" = 0 deg
extrude "Extrusion158" new body sketch "Sketch5" distance "d380" = 115 (derived); taper "d381" = 0 deg
extrude "Extrusion159" new body sketch "Sketch5" distance "d382" = 115 (derived); taper "d383" = 0 deg
extrude "Extrusion160" new body sketch "Sketch5" distance "d384" = 115 (derived); taper "d385" = 0 deg
extrude "Extrusion161" new body sketch "Sketch5" distance "d386" = 115 (derived); taper "d387" = 0 deg
extrude "Extrusion162" new body sketch "Sketch5" distance "d388" = 115 (derived); taper "d389" = 0 deg
workplane "Work Plane4"
workplane "Work Plane5"
sketch "Sketch6"
  geometry: L1 (-412.081, 126)-(-489.238, -68) reference; L2 (-101.896, 136)-(-123.689, 190.794) reference; L3 (-20.762, -68)-(-97.919, 126) reference; L4 (-489.238, -68)-(-20.762, -68) reference; L5 (-386.311, 190.794)-(-408.104, 136) reference; L6 (-20.762, -68)-(-123.689, 190.794); L7 (-97.919, 126)-(-20.762, -68) reference; L8 (-20.762, -68)-(-489.238, -68); L9 (-489.238, -68)-(-386.311, 190.794); L10 (-395.798, 194)-(-418.865, 136) reference; A1 r 425 centre (-255, 595) between (-386.311, 190.794) and (-260, 170.029) reference; A2 r 425 centre (-255, 595) between (-250, 170.029) and (-123.689, 190.794) reference; A3 r 425 centre (-255, 595) between (-386.311, 190.794) and (-123.689, 190.794); 1 further point
  constraints: 6 end point, 2 collinear, 2 point on circle, 1 centre point, 1 parallel
extrude "Extrusion163" new body sketch "Sketch6" distance "d392" = 135; taper "d393" = 0 deg
workplane "Work Plane6"
sketch "Sketch7"
  geometry: L1 (-11.979, 117.796)-(-0.303, 60.983) reference; L2 (0, 58)-(0, 0) reference; L3 (0, 29)-(-300, 29); L4 (-6.141, 89.39)-(-300, 29); L5 (115, 0)-(115, 58) reference; C1 r 310 at (-300, 29); C2 r 405 at (-300, 29); 1 further point
  constraints: 4 end point, 2 centre point, 2 coincident, 2 midpoint, 1 horizontal, 1 perpendicular
  dimensions: "d395" = 10 distance edge to line of C1 L1; "d396" = 10 distance edge to line of C2 L5 (derived)
extrude "Extrusion164" join sketch "Sketch7" distance "d397" = 95; taper "d398" = 0 deg
workplane "Work Plane7"
sketch "Sketch8"
  geometry: L1 (-165.38, 874)-(-146.792, 816) reference; L2 (-10, 738)-(-250, 738) reference; L3 (1740, 874)-(1655.38, 874) reference; L4 (1633.588, 806)-(1625, 779.204) reference; L5 (1740, 738)-(1500, 738) reference; L6 (1740, 874)-(1740, -612); L7 (1740, -612)-(-250, -612); L8 (-250, -612)-(-250, 874); L9 (-250, 874)-(-165.38, 874); L10 (-165.38, 874)-(-124.847, 747.523); L11 (1740, 874)-(1655.38, 874); L12 (1655.38, 874)-(1614.847, 747.523); L13 (1655.38, 874)-(1636.792, 816) reference; C1 r 405 at (745, 51) reference; C2 r 436.685 at (745, 51); A1 r 2840.721 centre (745, -1966.721) between (115, 803.26) and (-91.651, 748) reference; A2 r 2840.721 centre (745, -1966.721) between (1581.651, 748) and (1375, 803.26) reference; A3 r 2767.321 centre (745, -1890.066) between (1611.795, 738) and (-121.795, 738); A4 r 2777.321 centre (745, -1890.066) between (1614.847, 747.523) and (-124.847, 747.523) reference; A5 r 2881.211 centre (745, -1890.066) between (1646.554, 846.46) and (-156.554, 846.46)
  constraints: 14 end point, 6 point on circle, 4 centre point, 4 point on line, 3 perpendicular, 2 collinear, 1 coincident, 1 horizontal, 1 vertical, 1 other
  dimensions: "d400" = 10 radial gap between concentric circles of A3 A4
extrude "Extrusion165" join sketch "Sketch8" distance "d401" = 95; taper "d402" = 0 deg
sketch "Sketch9"
  geometry: C1 r 405 at (-745, 51) reference; C2 r 435 at (-745, 51); A1 r 425 centre (-745, 51) between (-1169.942, 58) and (-1166.929, 0) reference; 1 further point
  constraints: 1 centre point, 1 coincident
  dimensions: "d405" = 10 radial gap between concentric circles of C2 A1
extrude "Extrusion166" cut sketch "Sketch9" stored distance "d403" = 215; taper "d404" = 0 deg
extrude "Extrusion167" join sketch "Sketch8" distance "d406" = 80; taper "d408" = 0 deg; dims "d407" = 15, "d409" = 0
sketch "Sketch10"
  geometry: L1 (-1490, 330)-(-1250, 330) reference; L2 (-1422, 330)-(-1422, 679.817); L3 (-1422, 679.817)-(-1500.197, 679.817); L4 (-1500.197, 679.817)-(-1500.197, 407.908); L5 (-1490, 670)-(-1490, 510) reference; L6 (-1500.197, 407.908)-(-1625, 407.908); L7 (-1625, 407.908)-(-1625, 330); L8 (-1625, 330)-(-1422, 330); L9 (-1365, 398)-(-1125, 398) reference; L10 (-1125, 748)-(-1365, 748) reference; L11 (-1172, 398)-(-1250, 398); L12 (-1250, 398)-(-1250, 748); L13 (-1250, 748)-(-1172, 748); L14 (-1172, 748)-(-1172, 398); L15 (-750, 816)-(-990, 816) reference; L16 (-1000, 466.079)-(-797, 466.079); L17 (-797, 466.079)-(-797, 816); L18 (-797, 816)-(-1000, 816); L19 (-1000, 816)-(-1000, 466.079); L20 (-490, 816)-(-704, 816); L21 (-704, 816)-(-704, 466.079); L22 (-704, 466.079)-(-490, 466.079); L23 (-490, 466.079)-(-490, 816); L24 (-125, 748)-(-365, 748) reference; L25 (-171.226, 748)-(-375, 748); L26 (-375, 748)-(-375, 398); L27 (-375, 398)-(-171.226, 398); L28 (-171.226, 398)-(-171.226, 748); L29 (-240, 330)-(0, 330) reference; L30 (135, 679.817)-(-68.82, 679.817); L31 (-68.82, 679.817)-(-68.82, 330); L32 (-68.82, 330)-(135, 330); L33 (135, 330)-(135, 679.817); 1 further point
  constraints: 52 end point, 11 parallel, 9 perpendicular, 8 point on line, 5 horizontal, 1 vertical
extrude "Extrusion168" cut sketch "Sketch10" distance "d410" = 1; taper "d411" = 0 deg
node "Direct Edit1"
node "M2.1"
pattern_circular "Circular Pattern1" dims "d275" = 360 deg
node "M2.2"
node "M2.3"
node "M2.4"
node "M2.5"
node "M2.7"
node "M2.8"
node "M2.9"
node "M2.10"
node "M2.11"
node "M2.12"
node "M2.13"
node "M2.14"
node "M2.15"
feature "Pattern of M2.15:1"
node "M2.16"
feature "Pattern of M2.15:2"
node "M2.17"
feature "Pattern of M2.15:3"
node "M2.18"
feature "Pattern of M2.15:4"
node "M2.19"
feature "Pattern of M2.15:5"
node "M2.20"
feature "Pattern of M2.15:6"
node "M2.21"
feature "Pattern of M2.15:7"
node "M2.22"
feature "Pattern of M2.15:8"
node "M2.23"
feature "Pattern of M2.15:9"
node "M2.24"
feature "Pattern of M2.15:10"
node "M2.25"
feature "Pattern of M2.15:11"
node "M2.26"
feature "Pattern of M2.15:12"
node "M2.27"
feature "Pattern of M2.15:13"
node "M2.28"
feature "Pattern of M2.15:14"
node "M2.29"
feature "Pattern of M2.15:15"
node "M2.30"
feature "Pattern of M2.15:16"
node "M2.31"
feature "Pattern of M2.15:17"
node "M2.32"
feature "Pattern of M2.15:18"
node "M2.33"
feature "Pattern of M2.15:19"
node "M2.34"
feature "Pattern of M2.15:20"
node "M2.35"
feature "Pattern of M2.15:21"
node "M2.36"
feature "Pattern of M2.15:22"
node "M2.37"
feature "Pattern of M2.15:23"
node "M2.38"
feature "Pattern of M2.15:24"
node "M2.39"
feature "Pattern of M2.15:25"
node "M2.40"
feature "Pattern of M2.15:26"
node "M2.41"
feature "Pattern of M2.15:27"
node "M2.42"
feature "Pattern of M2.15:28"
node "M2.43"
feature "Pattern of M2.15:29"
node "M2.44"
feature "Pattern of M2.15:30"
body "Solid45"
feature "Pattern of M2.15:31"
body "Solid46"
feature "Pattern of M2.15:32"
body "Solid47"
feature "Pattern of M2.15:33"
body "Solid48"
feature "Pattern of M2.15:34"
body "Solid49"
body "Solid50"
body "Solid51"
body "Solid52"
feature "Pattern of M2.15:35"
body "Solid53"
feature "Pattern of M2.15:36"
body "Solid54"
feature "Pattern of M2.15:37"
body "Solid55"
feature "Pattern of M2.15:38"
body "Solid56"
feature "Pattern of M2.15:39"
body "Solid57"
feature "Pattern of M2.15:40"
body "Solid58"
feature "Pattern of M2.15:41"
body "Solid59"
feature "Pattern of M2.15:42"
body "Solid60"
feature "Pattern of M2.15:43"
body "Solid61"
feature "Pattern of M2.15:44"
body "Solid62"
feature "Pattern of M2.15:45"
body "Solid63"
feature "Pattern of M2.15:46"
body "Solid64"
feature "Pattern of M2.15:47"
body "Solid65"
feature "Pattern of M2.15:48"
body "Solid66"
feature "Pattern of M2.15:49"
body "Solid67"
feature "Pattern of M2.15:50"
body "Solid68"
feature "Pattern of M2.15:51"
body "Solid69"
feature "Pattern of M2.15:52"
body "Solid70"
feature "Pattern of M2.15:53"
body "Solid71"
feature "Pattern of M2.15:54"
body "Solid72"
feature "Pattern of M2.15:55"
body "Solid73"
feature "Pattern of M2.15:56"
body "Solid74"
feature "Pattern of M2.15:57"
body "Solid75"
feature "Pattern of M2.15:58"
body "Solid76"
feature "Pattern of M2.15:59"
body "Solid77"
feature "Pattern of M2.15:60"
node "M2.78"
feature "Pattern of M2.15:61"
node "M2.79"
feature "Pattern of M2.15:62"
node "M2.80"
body "Solid81"
body "Solid82"
body "Solid83"
body "Solid84"
body "Solid87"
body "Solid88"
body "Solid89"
body "Solid90"
body "Solid91"
body "Solid92"
body "Solid93"
body "Solid94"
body "Solid95"
body "Solid96"
body "Solid97"
body "Solid98"
body "Solid99"
body "Solid100"
body "Solid101"
body "Solid102"
body "Solid103"
body "Solid104"
body "Solid105"
body "Solid106"
body "Solid107"
body "Solid108"
body "Solid109"
body "Solid110"
body "Solid111"
body "Solid112"
body "Solid113"
body "Solid114"
body "Solid115"
feature "Pattern of M2.15:63"
body "Solid116"
feature "Pattern of M2.15:64"
body "Solid117"
body "Solid118"
body "Solid119"
body "Solid120"
body "Solid121"
body "Solid122"
body "Solid123"
body "Solid124"
body "Solid125"
body "Solid126"
body "Solid127"
body "Solid128"
body "Solid129"
body "Solid130"
body "Solid131"
body "Solid132"
body "Solid133"
body "Solid134"
feature "Pattern of M2.15:65"
body "Solid135"
feature "Pattern of M2.15:66"
body "Solid136"
feature "Pattern of M2.15:67"
body "Solid137"
feature "Pattern of M2.15:68"
body "Solid138"
feature "Pattern of M2.15:69"
body "Solid139"
feature "Pattern of M2.15:70"
body "Solid140"
feature "Pattern of M2.15:71"
body "Solid141"
feature "Pattern of M2.15:72"
body "Solid142"
feature "Pattern of M2.15:73"
body "Solid143"
body "Solid144"
body "Solid145"
body "Solid146"
body "Solid147"
body "Solid148"
body "Solid149"
body "Solid150"
body "Solid151"
body "Solid152"
body "Solid153"
body "Solid154"
body "Solid155"
body "Solid156"
body "Solid157"
body "Solid158"
body "Solid159"
body "Solid160"
body "Solid161"
body "Solid162"
body "Solid163"
body "Solid164"
body "Solid165"
body "Solid166"
body "Solid167"
body "Solid168"
body "Solid169"
body "Solid170"
body "Solid171"
body "Solid172"
body "Solid173"
body "Solid174"
body "Solid175"
body "Solid176"
body "Solid177"
body "Solid178"
body "Solid179"
body "Solid180"
body "Solid181"
body "Solid182"
feature "Pattern of M2.44:74"
body "Solid183"
feature "Pattern of M2.44:75"
body "Solid184"
feature "Pattern of M2.44:76"
body "Solid185"
feature "Pattern of M2.44:77"
body "Solid186"
feature "Pattern of M2.44:78"
body "Solid187"
feature "Pattern of M2.44:79"
body "Solid188"
feature "Pattern of M2.44:80"
body "Solid189"
feature "Pattern of M2.44:81"
body "Solid190"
